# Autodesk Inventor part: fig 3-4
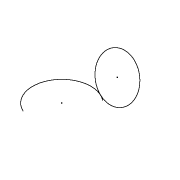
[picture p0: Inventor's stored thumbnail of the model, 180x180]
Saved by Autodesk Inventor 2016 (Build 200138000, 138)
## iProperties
Created: 2009-11
Part Number: fig 3-4
Document SubType Name: Modeling
Designer: Sham
Density: 1 g/cm^3
Material: Generic
Appearance: Default
Author: Sham
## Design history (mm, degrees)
sketch "Sketch1"
  geometry: A1 r 10.623 centre (-1.113, -21.203) between (5.463, -12.861) and (-5.537, -30.861); 1 further point; 1 other entity
  constraints: 2 point on circle, 1 centre point, 4 other
